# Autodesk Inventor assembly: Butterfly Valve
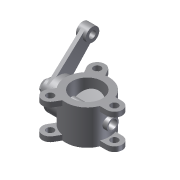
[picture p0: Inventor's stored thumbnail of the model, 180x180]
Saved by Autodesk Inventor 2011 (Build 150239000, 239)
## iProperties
Created: 2009-04
Part Number: Butterfly Valve
Document SubType Name: Assembly
Designer: Sham
Author: Sham
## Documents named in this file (8)
- C:\Users\CADSoft\Desktop\part files\c09-inv-2011-prt\Butterfly Valve\Butterfly Valve.iam
- C:\Inventor_2011\c09_inv_2011_02062010\Butterfly Valve\Body.ipt
- C:\Inventor_2011\c09_inv_2011_02062010\Butterfly Valve\Shaft.ipt
- C:\Inventor_2011\c09_inv_2011_02062010\Butterfly Valve\Retainer.ipt
- C:\Inventor_2011\c09_inv_2011_02062010\Butterfly Valve\Arm.ipt
- C:\Inventor_2011\c09_inv_2011_02062010\Butterfly Valve\Plate.ipt
- C:\Inventor_2011\c09_inv_2011_02062010\Butterfly Valve\Screw.ipt
- C:\Inventor_2011\c09_inv_2011_02062010\Butterfly Valve\Nut.ipt
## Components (9 placed, 7 different names)
1. Body:1 — Insert:1, Angle:1, Insert:2, Mate:1, Angle:2
2. Shaft:1 — Insert:1, Angle:1, Insert:4, Insert:5, Insert:9
3. Retainer:1 — Insert:2, Mate:1, Insert:3, Insert:6, Insert:7, Insert:8
4. Arm:1 — Insert:3, Angle:2
5. Plate:1 — Insert:4, Insert:5
6. Screw:1 — Insert:6
7. Screw:2 — Insert:7
8. Screw:3 — Insert:8
9. Nut:1 — Insert:9
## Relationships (12: Insert 9, Angle 2, Mate 1)
- Insert:1: Body:1 ↔ Shaft:1
- Angle:1: Body:1 ↔ Shaft:1
- Insert:2: Body:1 ↔ Retainer:1
- Mate:1: Body:1 ↔ Retainer:1
- Insert:3: Retainer:1 ↔ Arm:1
- Angle:2: Body:1 ↔ Arm:1
- Insert:4: Shaft:1 ↔ Plate:1
- Insert:5: Shaft:1 ↔ Plate:1
- Insert:6: Retainer:1 ↔ Screw:1
- Insert:7: Retainer:1 ↔ Screw:2
- Insert:8: Retainer:1 ↔ Screw:3
- Insert:9: Shaft:1 ↔ Nut:1
